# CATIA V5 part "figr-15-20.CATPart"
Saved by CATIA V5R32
Part number: Part1
Bounding box of the stored display mesh (mm): x -81.56 to 85.56, y -36.965 to 25.965, z 0 to 42
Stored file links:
  D:\PROJECTS\Project 2022\CATIA V5 6R 2022\Resources\Part Files\c15_catia_v5_6r2022_prt\figr-15-20.CATPart
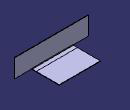
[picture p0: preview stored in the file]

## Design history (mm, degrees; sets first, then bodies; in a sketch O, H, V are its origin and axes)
SheetMetalParameters1: Thickness 1, BendRadius 1, KFactor 0.325257 {= log(min(100,max(20*SheetMetalParameters1.BendRadius,SheetMetalParameters1.Thickness)/SheetMetalParameters1.Thickness))/log(100)/2}, ReliefRadialLength 1, ReliefAxialLength 2, MinimumBendRadius 0
Body1 (main body)
  Sketch1 on xy-plane, origin (0, 0, 0), H (1, 0, 0), V (0, 1, 0)
    line L1 (-46.5596, 25.9646) -> (46.5596, 25.9646)
    line L2 (46.5596, 25.9646) -> (46.5596, -25.9646)
    line L3 (46.5596, -25.9646) -> (-46.5596, -25.9646)
    line L4 (-46.5596, -25.9646) -> (-46.5596, 25.9646)
    horizontal: L1 H, L3 H
    vertical: L2 V, L4 V
    symmetry: L1 L3 H, L4 L2 V
  Wall1: Thickness 1, Profile Sketch1
  d_NewWallOnEdge1: NewWallOnEdge_Edge edge [face of Wall1 | face of Wall1], NewWallOnEdge_Length 42, NewWallOnEdge_HeightLimitOffset 0, NewWallOnEdge_WidthOffset1 39, NewWallOnEdge_WidthOffset2 35, NewWallOnEdge_Angle 90, NewWallOnEdge_BendRadiusValue 1 {= SheetMetalParameters1.BendRadius}, NewWallOnEdge_BendTable SheetMetalParameters1, KFacteur 0.325257 {= log(min(100,max(20*d_NewWallOnEdge1.Radius,SheetMetalParameters1.Thickness)/SheetMetalParameters1.Thickness))/log(100)/2}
